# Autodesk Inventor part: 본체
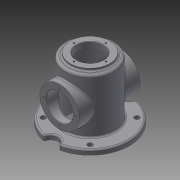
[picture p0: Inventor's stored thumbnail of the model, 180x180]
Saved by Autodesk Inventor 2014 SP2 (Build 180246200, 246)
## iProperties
Created: 2018-04
Part Number: 본체
Material: Generic
Document SubType Name: Modeling
Designer: 거성
Density: 1 g/cm^3
Appearance: Default
Author: 거성
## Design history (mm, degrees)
sketch "스케치1"
  geometry: A1 r 15 centre (80, 0) between (78.594, 14.934) and (78.594, -14.934); A2 r 15 centre (-80, 0) between (-78.594, -14.934) and (-78.594, 14.934); A3 r 80 centre (0, 0) between (-78.594, -14.934) and (78.594, -14.934); A4 r 80 centre (0, 0) between (78.594, 14.934) and (-78.594, 14.934); 1 further point
  constraints: 8 point on circle, 4 centre point, 2 horizontal alignment, 1 coincident
  dimensions: "d1" = 30 diameter of A2; "d2" = 30 diameter of A1
extrude "돌출1" new body sketch "스케치1" distance "d3" = 10; taper "d4" = 0 deg
sketch "스케치2"
  geometry: C1 r 50 at (0, 0); A1 r 80 centre (0, 0) between (78.594, 14.934) and (-78.594, 14.934) reference
  constraints: 1 centre point, 1 concentric
  dimensions: "d5" = 100 diameter of C1
extrude "돌출2" join sketch "스케치2" distance "d6" = 110; taper "d7" = 0 deg
sketch "스케치3"
  geometry: C1 r 50 at (0, 0) reference; C2 r 40 at (0, 0)
  constraints: 1 centre point, 1 concentric
  dimensions: "d8" = 80 diameter of C2
extrude "돌출3" join sketch "스케치3" distance "d9" = 5; taper "d10" = 0 deg
sketch "스케치5"
  geometry: C1 r 50 at (0, 0); A1 r 80 centre (0, 0) between (78.594, 14.934) and (-78.594, 14.934) reference
  constraints: 1 centre point, 1 concentric
  dimensions: "d15" = 100 diameter of C1
extrude "돌출5" join sketch "스케치5" distance "d16" = 8; taper "d17" = 0 deg
sketch "스케치6" dims "d18" = 135
  geometry: L1 (0, 0)-(-75.007, 75.007); L2 (0, 0)-(-110.102, 0); A1 r 80 centre (0, 0) between (78.594, 14.934) and (-78.594, 14.934) reference; 1 further point
  constraints: 4 end point, 1 horizontal, 1 point on line, 4 other
  dimensions: "d19" = 45 deg angle of L2 L1
hole "구멍1" sketch "스케치6" at (-47.73, 47.73) diameter "d20" = 10; stored, may be unused: countersink angle "d24" = 90 deg, drill point angle "d26" = 118 deg; dims "d21" = 6, "d22" = 4, "d23" = 2, "d25" = 8
sketch "스케치7"
  geometry: C1 r 40 at (60, 0); 1 further point
  constraints: 1 centre point, 1 horizontal alignment
  dimensions: "d30" = 60 distance of C1.centre point (0, 0); "d31" = 80 diameter of C1
extrude "돌출6" join sketch "스케치7" stored distance "d32" = 124; taper "d33" = 0 deg
hole "구멍2" diameter "d36" = 54; stored, may be unused: countersink angle "d40" = 90 deg, drill point angle "d42" = 118 deg; dims "d34" = 10, "d35" = 10, "d37" = 6, "d38" = 4, "d39" = 2, "d41" = 8
hole "구멍3" diameter "d45" = 54; stored, may be unused: countersink angle "d49" = 90 deg, drill point angle "d51" = 0 deg; dims "d43" = 10, "d44" = 10, "d46" = 6, "d47" = 4, "d48" = 2, "d50" = 13
hole "구멍4" diameter "d54" = 90; stored, may be unused: countersink angle "d58" = 90 deg, drill point angle "d60" = 0 deg; dims "d52" = 10, "d53" = 10, "d55" = 6, "d56" = 4, "d57" = 2, "d59" = 120
sketch "스케치8" dims "d61" = 65
  geometry: C1 r 27 at (0, 0) reference; C2 r 40 at (0, 0) reference; 2 further points
  constraints: 2 vertical alignment, 3 other
hole "구멍5" sketch "스케치8" at (0, 32.5) diameter "d62" = 3.242; stored, may be unused: countersink angle "d66" = 90 deg, drill point angle "d68" = 118 deg; dims "d63" = 8, "d64" = 4, "d65" = 2, "d67" = 10
sketch "스케치9" dims "d72" = 65
  geometry: C1 r 27 at (0, 0) reference; C2 r 40 at (0, 0) reference; 3 further points
  constraints: 2 vertical alignment, 3 other
hole "구멍6" sketch "스케치9" at (0, 32.5) diameter "d73" = 3.242; stored, may be unused: countersink angle "d77" = 90 deg, drill point angle "d79" = 118 deg; dims "d74" = 8, "d75" = 4, "d76" = 2, "d78" = 10
sketch "스케치10"
  geometry: C1 r 40 at (0, 0) reference; C2 r 32.5 at (0, 0); C3 r 1.621 at (0, 32.5) reference; 2 further points
  constraints: 1 centre point, 1 coincident, 1 concentric
  dimensions: "d83" = 65 diameter of C2
hole "구멍7" sketch "스케치10" at (0, 32.5) diameter "d84" = 3.242; stored, may be unused: countersink angle "d88" = 90 deg, drill point angle "d90" = 118 deg; dims "d85" = 8, "d86" = 4, "d87" = 2, "d89" = 10
fillet "모깎기1" dims "d94" = 5
fillet "모깎기2" dims "d95" = 3
fillet "모깎기3" dims "d96" = 3
chamfer "모따기1" distance "d97" = 1; stored, may be unused: second distance "d98" = 2, angle "d99" = 45 deg
node "작업 평면1"
sketch "스케치11"
  geometry: L1 (-3.5, 46)-(-3.5, 94); L2 (-3.5, 94)-(3.5, 94); L3 (3.5, 94)-(3.5, 46); L4 (3.5, 46)-(-3.5, 46); L5 (0, 46)-(0, 94); L6 (-3.5, 70)-(3.5, 70); 1 further point
  constraints: 4 end point, 4 midpoint, 1 vertical alignment, 2 other
  dimensions: "d101" = 7 distance between parallel lines of L3 L1; "d102" = 48 distance between parallel lines of L2 L4; "d103" = 70 distance from line of L6 point (0, 0)
feature "엠보싱1" sketch "스케치11" dims "d104" = 0.5, "d105" = 0
node "솔리드1"
pattern_circular "원형 패턴1" dims angle "d28" = 360 deg
pattern_circular "원형 패턴2" dims angle "d70" = 360 deg
pattern_circular "원형 패턴3" dims angle "d81" = 360 deg
pattern_circular "원형 패턴4" dims angle "d92" = 360 deg
other parameters: "d100" = -92.075
